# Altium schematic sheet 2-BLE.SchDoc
size A3; SheetNumber: 7; SheetTotal: 7
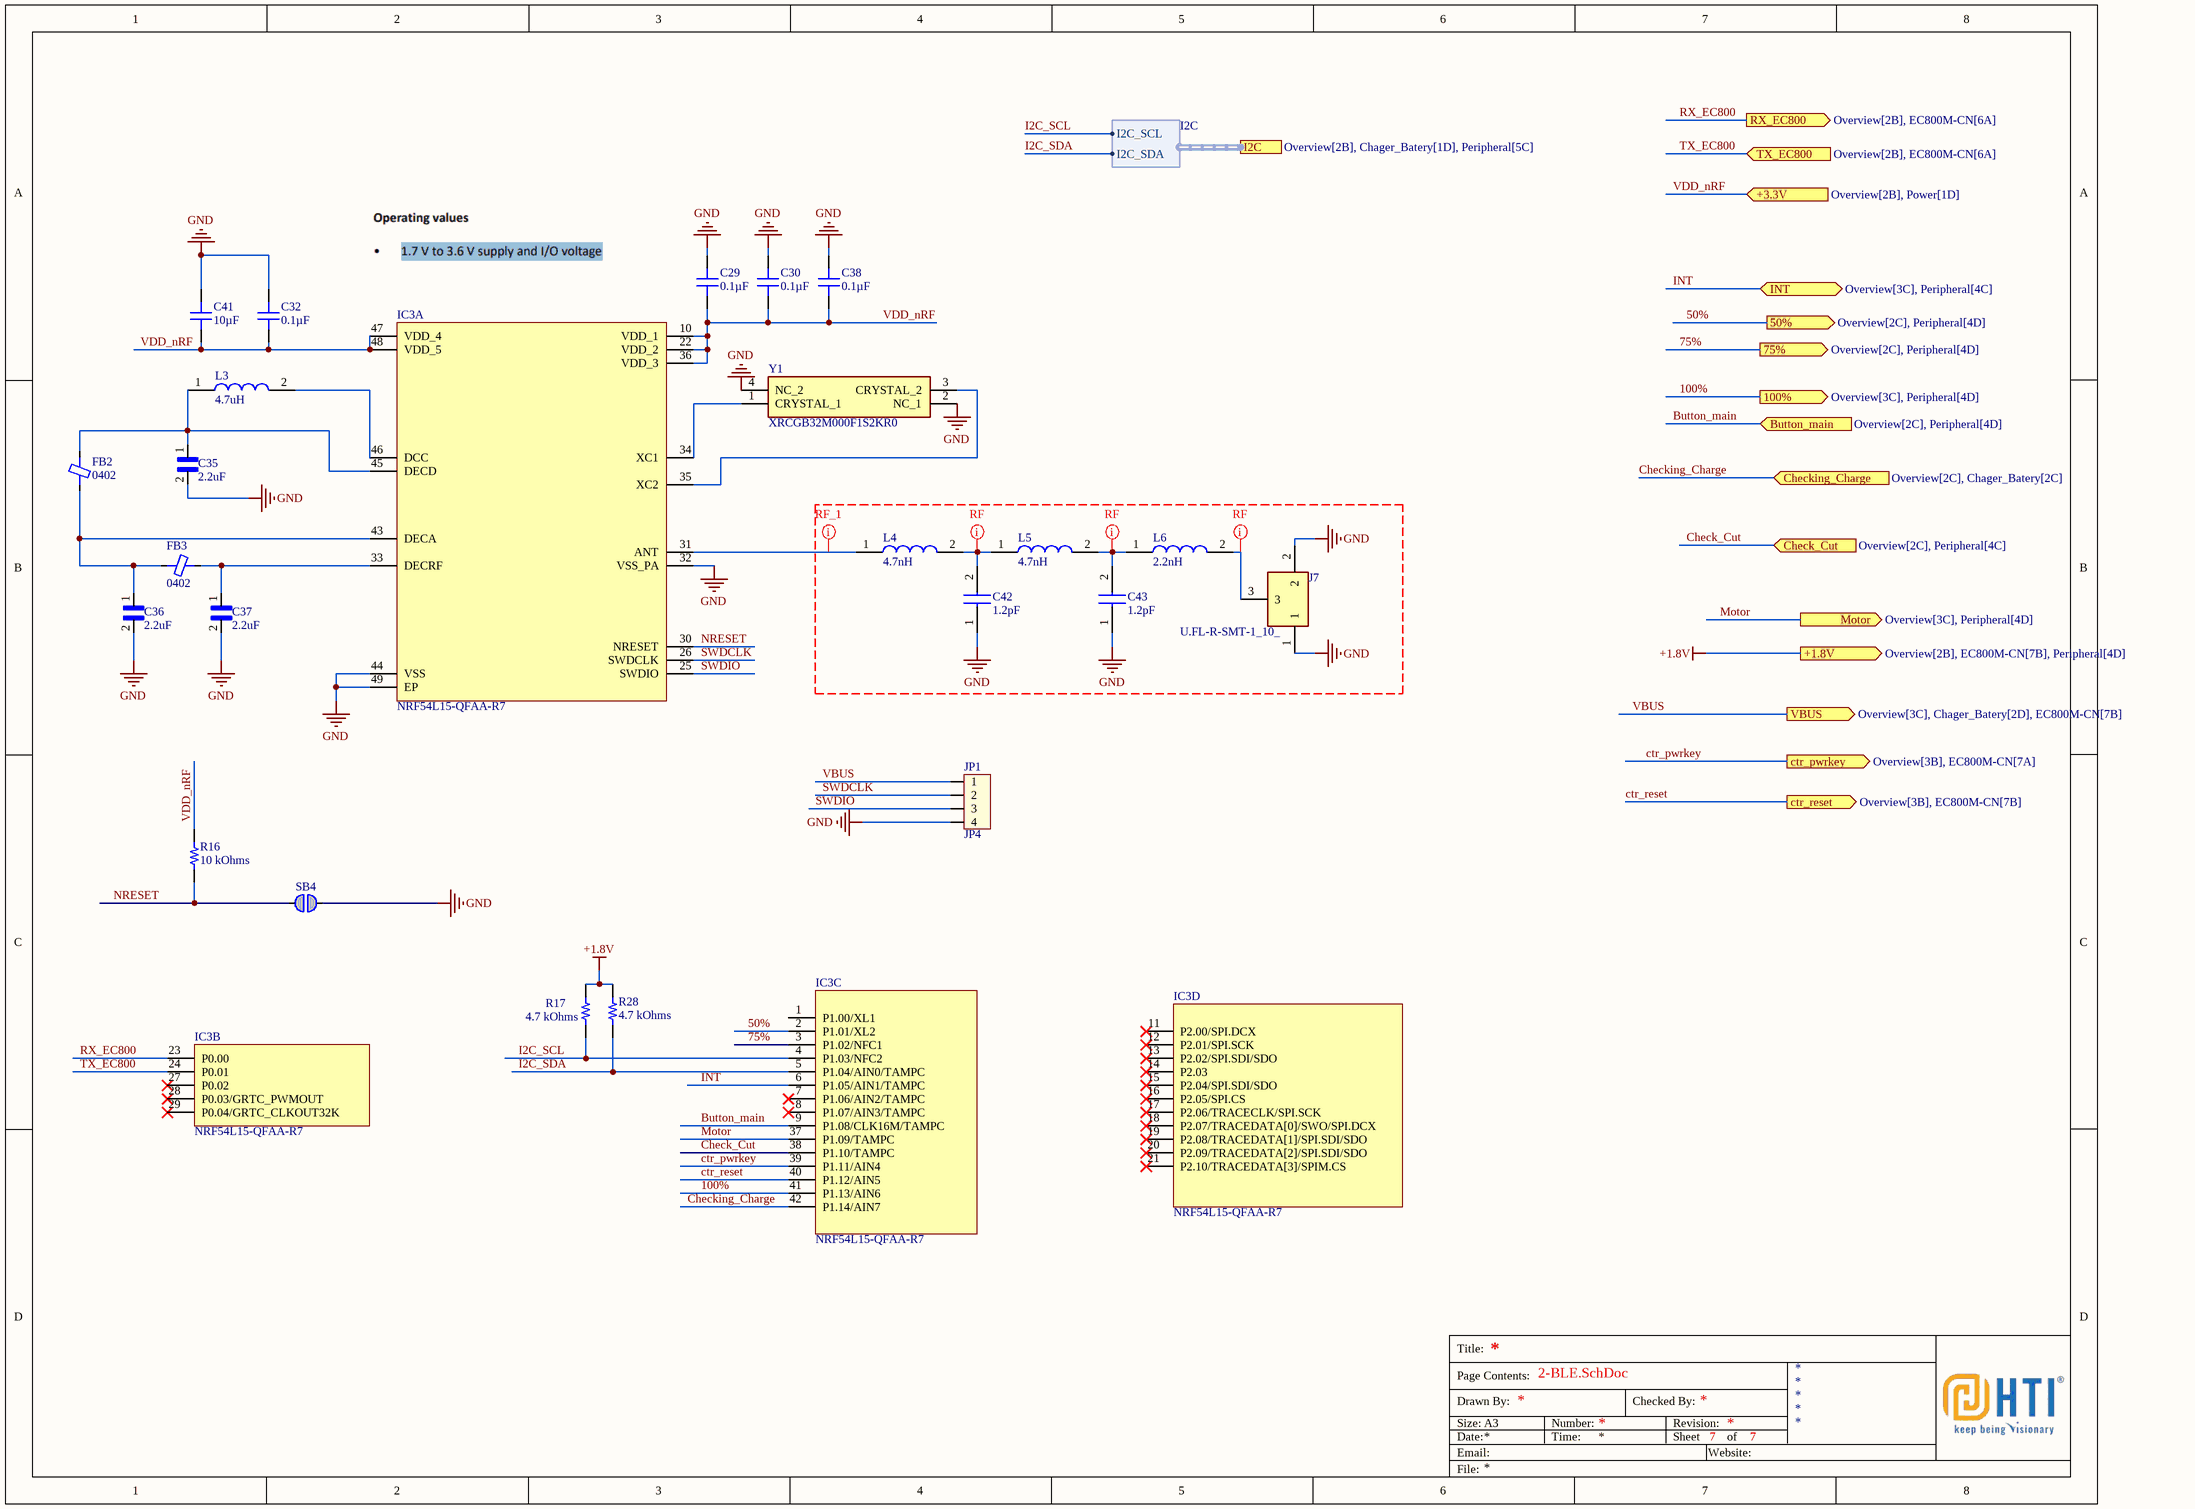
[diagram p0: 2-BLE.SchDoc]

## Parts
C29  0.1µF  [CAP 0402_1005]
C30  0.1µF  [CAP 0402_1005]
C32  0.1µF  [CAP 0402_1005]
C35  2.2uF  [CAP 0402_1005]
C36  2.2uF  [CAP 0402_1005]
C37  2.2uF  [CAP 0402_1005]
C38  0.1µF  [CAP 0402_1005]
C41  10µF  [CAP 0402_1005]
C42  1.2pF  [CAPC1005X70N]
C43  1.2pF  [CAPC1005X70N]
FB2  0402  [BMCQ1E0000H]
FB3  0402  [BMCQ1E0000H]
IC3  NRF54L15-QFAA-R7  [QFN40P600X600X90-49N-D]  (parts A,B,C,D of 4)
J7  U.FL-R-SMT-1_10_  [U.FL-R-SMT-1(10)]
JP1  JP4  [CON4 - duplicate]
L3  4.7uH  [PLEA67BCA4R7M1PT00]
L4  4.7nH  [LQW15CNR20J00B]
L5  4.7nH  [LQW15CNR20J00B]
L6  2.2nH  [LQW15AN10NG80D]
R16  10 kOhms  [RES 0402_1005]
R17  4.7 kOhms  [RES 0402_1005]
R28  4.7 kOhms  [RES 0402_1005]
SB4  Solderbridge  [Solderbridge]  (value not drawn)  (no BOM)
Y1  XRCGB32M000F1S2KR0  [XRCGB32M000F1S2KR0]

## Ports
50% (out, see Overview[2C], Peripheral[4D]), 75% (out, see Overview[2C], Peripheral[4D]), 100% (out, see Overview[3C], Peripheral[4D]), +1.8V (out, see Overview[2B], EC800M-CN[7B], Peripheral[4D]), +3.3V (in, see Overview[2B], Power[1D]), Button_main (in, see Overview[2C], Peripheral[4D]), Check_Cut (in, see Overview[2C], Peripheral[4C]), Checking_Charge (in, see Overview[2C], Chager_Batery[2C]), ctr_pwrkey (out, see Overview[3B], EC800M-CN[7A]), ctr_reset (out, see Overview[3B], EC800M-CN[7B]), I2C (harness I2C, see Overview[2B], Chager_Batery[1D], Peripheral[5C]), INT (bidir, see Overview[3C], Peripheral[4C]), Motor (out, see Overview[3C], Peripheral[4D]), RX_EC800 (out, see Overview[2B], EC800M-CN[6A]), TX_EC800 (in, see Overview[2B], EC800M-CN[6A]), VBUS (out, see Overview[3C], Chager_Batery[2D], EC800M-CN[7B])

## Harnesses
I2C: I2C_SCL, I2C_SDA

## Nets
+1.8V: R17.2 R28.2 ; port +1.8V
GND: C29.2 C30.2 C32.2 C35.2 C36.2 C37.2 C38.2 C41.2 C42.1 C43.1 IC3.32(VSS_PA) IC3.44(VSS) IC3.49(EP) J7.1 J7.2 JP1.4 SB4.1 Y1.2(NC_1) Y1.4(NC_2)
50%: IC3.2(P1.01/XL2) ; port 50%
75%: IC3.3(P1.02/NFC1) ; port 75%
100%: IC3.41(P1.13/AIN6) ; port 100%
Button_main: IC3.9(P1.08/CLK16M/TAMPC) ; port Button_main
Check_Cut: IC3.38(P1.10/TAMPC) ; port Check_Cut
Checking_Charge: IC3.42(P1.14/AIN7) ; port Checking_Charge
ctr_pwrkey: IC3.39(P1.11/AIN4) ; port ctr_pwrkey
ctr_reset: IC3.40(P1.12/AIN5) ; port ctr_reset
I2C_SCL: IC3.4(P1.03/NFC2) R17.1 ; port I2C.I2C_SCL
I2C_SDA: IC3.5(P1.04/AIN0/TAMPC) R28.1 ; port I2C.I2C_SDA
INT: IC3.6(P1.05/AIN1/TAMPC) ; port INT
Motor: IC3.37(P1.09/TAMPC) ; port Motor
NRESET: IC3.30(NRESET) R16.1 SB4.2
RX_EC800: IC3.23(P0.00) ; port RX_EC800
SWDCLK: IC3.26(SWDCLK) JP1.2
SWDIO: IC3.25(SWDIO) JP1.3
TX_EC800: IC3.24(P0.01) ; port TX_EC800
VBUS: JP1.1 ; port VBUS
VDD_nRF: C29.1 C30.1 C32.1 C38.1 C41.1 IC3.10(VDD_1) IC3.22(VDD_2) IC3.36(VDD_3) IC3.47(VDD_4) IC3.48(VDD_5) R16.2 ; port +3.3V
NetC35_1: C35.1 FB2.2 IC3.45(DECD) L3.1
NetC36_1: C36.1 FB2.1 FB3.2 IC3.43(DECA)
NetC37_1: C37.1 FB3.1 IC3.33(DECRF)
NetC42_2: C42.2 L4.2 L5.1
NetC43_2: C43.2 L5.2 L6.1
NetIC3_31: IC3.31(ANT) L4.1
NetIC3_34: IC3.34(XC1) Y1.1(CRYSTAL_1)
NetIC3_35: IC3.35(XC2) Y1.3(CRYSTAL_2)
NetIC3_46: IC3.46(DCC) L3.2
NetJ7_3: J7.3 L6.2

Not connected (* = marked no-connect by the designer): IC3 1(P1.00/XL1) 7(P1.06/AIN2/TAMPC)* 8(P1.07/AIN3/TAMPC)* 11(P2.00/SPI.DCX)* 12(P2.01/SPI.SCK)* 13(P2.02/SPI.SDI/SDO)* 14(P2.03)* 15(P2.04/SPI.SDI/SDO)* 16(P2.05/SPI.CS)* 17(P2.06/TRACECLK/SPI.SCK)* 18(P2.07/TRACEDATA[0]/SWO/SPI.DCX)* 19(P2.08/TRACEDATA[1]/SPI.SDI/SDO)* 20(P2.09/TRACEDATA[2]/SPI.SDI/SDO)* 21(P2.10/TRACEDATA[3]/SPIM.CS)* 27(P0.02)* 28(P0.03/GRTC_PWMOUT)* 29(P0.04/GRTC_CLKOUT32K)*

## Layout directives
net class RF: NetC42_2, NetC43_2, NetJ7_3
net class RF_1: NetIC3_31

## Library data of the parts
C29 C30 C32 C38 = CC0402MRX5R7BB104: CAP CER 0.1UF 16V X5R 0402; Manufacturer: Yageo; Tolerance: ±20%
C35-C37 = C0402C225M7PACTU: 2.2UF 4V 20% 0402; MF: {'manufacturer': u'KEMET'}
C41 = GRM155R60J106ME15D: CAP CER 10UF 6.3V X5R 0402; Manufacturer: Murata Electronics; Tolerance: ±20%
C42 C43 = GRM1555C1H1R2WA01D: Capacitor; Manufacturer_Name: Murata Electronics
FB2 FB3 = BMC-Q1E0000H: Ferrite Bead; Manufacturer_Name: TE Connectivity
IC3 = NRF54L15-QFAA-R7: Integrated Circuit; Manufacturer_Name: Nordic Semiconductor
J7 = U.FL-R-SMT-1_10_: Connector; Manufacturer_Name: Hirose
JP1 = Con4_1: Connector 4
L3 = PLEA67BCA4R7M-1PT00: Inductor; Manufacturer_Name: TDK
L4 L5 = LQW15AN4N7B8ZD: Inductor; Manufacturer_Name: Murata Electronics
L6 = LQW15AN2N2D80D: Inductor; Manufacturer_Name: Murata Electronics
R16 = AC0402JR-0710KL_1: RES SMD 10K OHM 5% 1/16W 0402; Manufacturer: Yageo; Power (Watts): 0.063W, 1/16W; Temperature Coefficient: ±100ppm/°C
R17 R28 = RC0402JR-074K7P: RES SMD 4.7K OHM 5% 1/16W 0402; Manufacturer: Yageo; Power (Watts): 0.063W, 1/16W; Temperature Coefficient: ±150ppm/°C
SB4 = Solderbridge: Manufacturer: N.A.; Pad Count: 2
Y1 = XRCGB32M000F1S2KR0: Crystal or Oscillator; Manufacturer_Name: Murata Electronics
